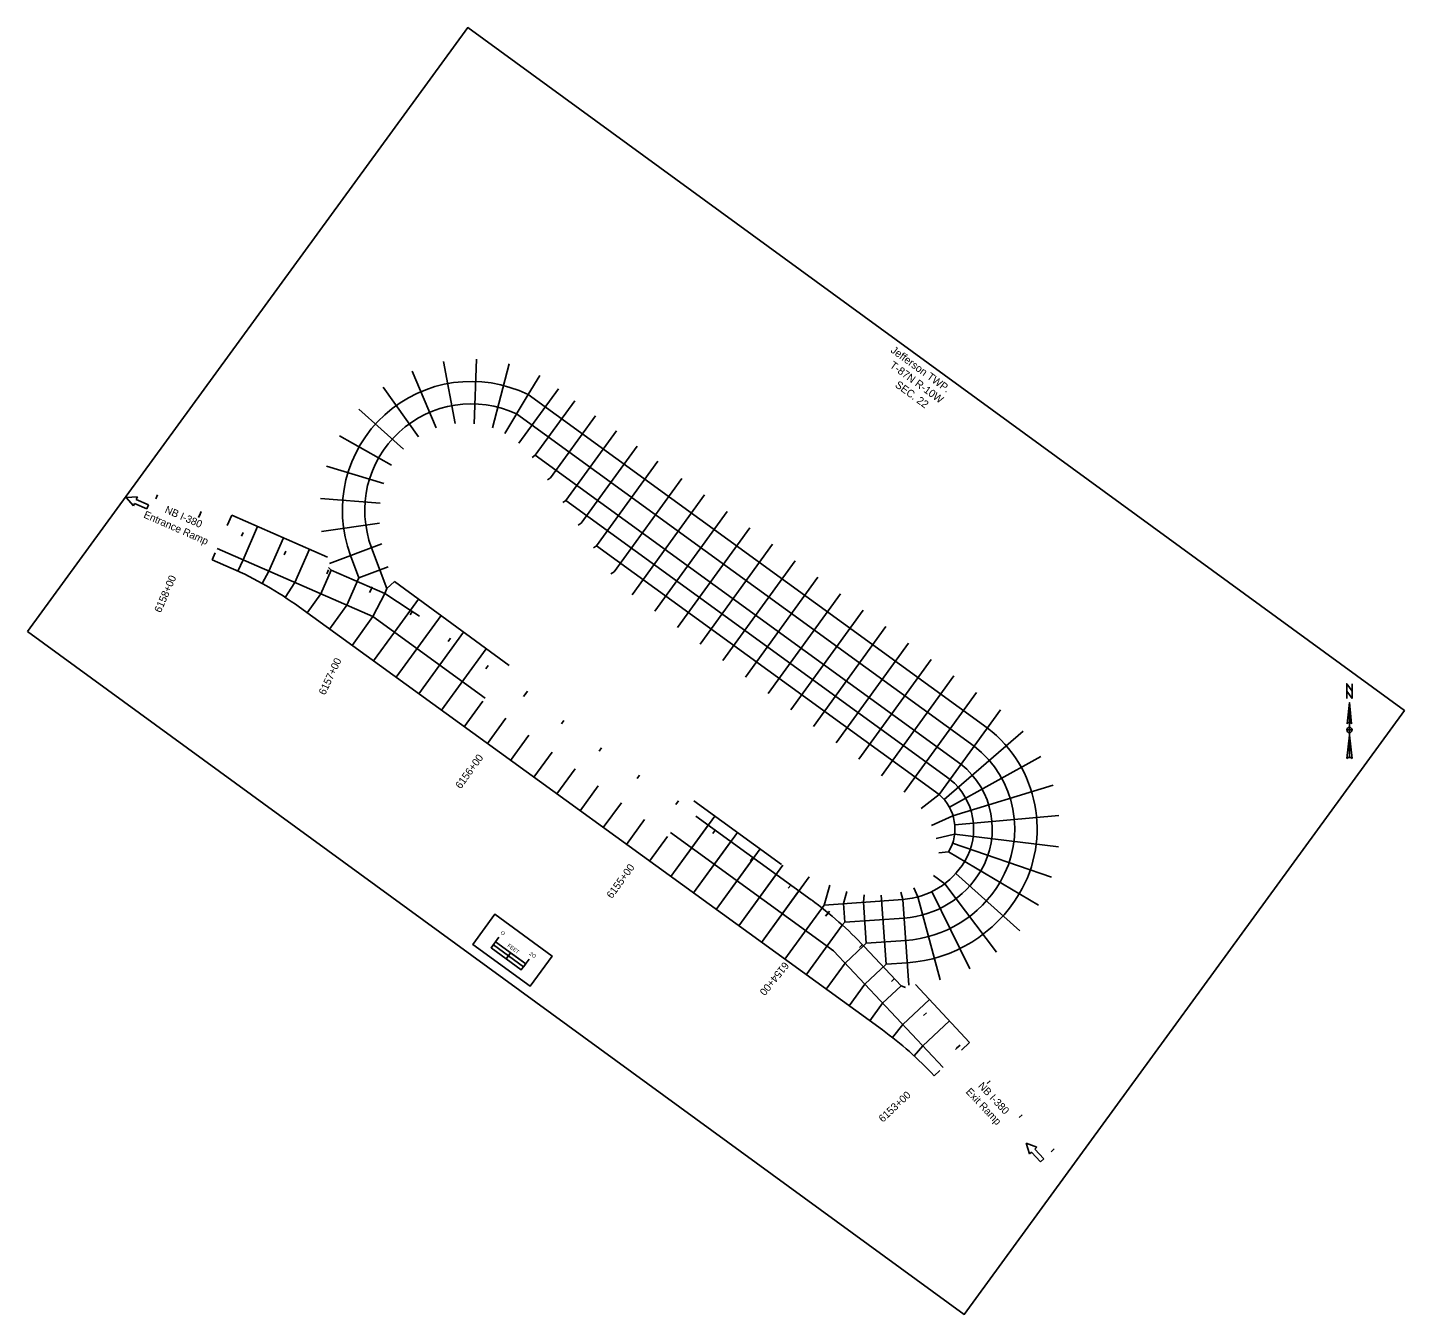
# Model space of a CAD drawing. Extents: x 15567747 to 15568484, y 8782920 to 8783608.
import ezdxf

# ---------------------------------------------------------------- set-up
doc = ezdxf.new("R2010")
doc.units = 0
for name, color, linetype in [('_CIVIL_CONSTRUCTION', 7, 'Continuous'), ('Alignment', 7, 'Continuous'), ('EdgeShoulder', 7, 'Continuous'), ('EXT_SH', 7, 'Continuous'), ('Joints', 7, 'Continuous'), ('Terrain', 7, 'Continuous'), ('Text', 7, 'Continuous'), ('TextAlignment', 7, 'Continuous'), ('TextAlignmentSml', 7, 'Continuous')]:
    doc.layers.add(name, color=color, linetype=linetype)

msp = doc.modelspace()

# ---------------------------------------------------------------- linework, layer by layer
at = {"layer": '_CIVIL_CONSTRUCTION'}
msp.add_lwpolyline([(15567746.92, 8783285.1), (15568248.32, 8782919.55), (15568483.96, 8783242.77), (15567982.56, 8783608.32)], close=True, dxfattribs=at)
at = {"layer": 'Alignment'}
for p, q in [((15567799.72, 8783356.86), (15567805.71, 8783357.17)), ((15567803.56, 8783352.25), (15567799.72, 8783356.86)), ((15567804.16, 8783353.62), (15567803.56, 8783352.25)), ((15567810.71, 8783350.75), (15567804.16, 8783353.62)), ((15567805.71, 8783357.17), (15567805.11, 8783355.8)), ((15567805.11, 8783355.8), (15567811.67, 8783352.93)), ((15567811.67, 8783352.93), (15567810.71, 8783350.75)), ((15568283.23, 8783005.44), (15568281.51, 8783011.19)), ((15568281.51, 8783011.19), (15568287.14, 8783009.12)), ((15568284.31, 8783006.46), (15568283.23, 8783005.44)), ((15568289.21, 8783001.25), (15568284.31, 8783006.46)), ((15568287.14, 8783009.12), (15568286.05, 8783008.1)), ((15568286.05, 8783008.1), (15568290.95, 8783002.88)), ((15568290.95, 8783002.88), (15568289.21, 8783001.25))]:
    msp.add_line(p, q, dxfattribs=at)
at = {"layer": 'EdgeShoulder'}
for p, q in [((15567856.21, 8783347.29), (15567853.8, 8783341.79)), ((15567907.4, 8783324.87), (15567856.21, 8783347.29)), ((15567845.8, 8783323.47), (15567847.4, 8783327.13)), ((15567855.98, 8783319.01), (15567845.8, 8783323.47)), ((15567943.42, 8783311.77), (15568004.64, 8783266.94)), ((15567892.42, 8783298.14), (15568204.49, 8783071.81)), ((15568150.43, 8783160.43), (15568103.49, 8783194.47)), ((15568251.21, 8783065.15), (15568222.15, 8783096.08)), ((15568251.21, 8783065.15), (15568246.84, 8783061.04)), ((15568232.26, 8783047.34), (15568235.18, 8783050.08))]:
    msp.add_line(p, q, dxfattribs=at)
for centre, start, end in [((15567777.35, 8783139.47), 54.04815, 66.34808), ((15568089.41, 8782913.14), 43.21229, 54.04815)]:
    msp.add_arc(centre, 196, start, end, dxfattribs=at)
at = {"layer": 'Joints'}
for p, q in [((15567975.79, 8783396.33), (15567969.6, 8783429.57)), ((15567986.01, 8783396.3), (15567987.19, 8783430.89)), ((15567995.79, 8783394.03), (15568004.64, 8783428.37)), ((15567965.68, 8783394.01), (15567952.72, 8783424.47)), ((15567956.26, 8783389.35), (15567937.34, 8783415.84)), ((15568009.92, 8783385.8), (15568031.07, 8783414.93)), ((15568014.89, 8783411.84), (15568260.68, 8783233.47)), ((15568018.69, 8783379.43), (15568039.83, 8783408.57)), ((15567948.12, 8783382.58), (15567924.19, 8783404.09)), ((15568008.71, 8783401.5), (15568253.63, 8783223.76)), ((15568026.88, 8783367.31), (15568050.96, 8783400.49)), ((15567941.75, 8783374.03), (15567913.9, 8783389.77)), ((15568035.07, 8783355.19), (15568062.09, 8783392.42)), ((15568043.26, 8783343.06), (15568073.22, 8783384.34)), ((15568018.69, 8783379.43), (15568017.05, 8783378.23)), ((15568018.69, 8783379.43), (15568246.58, 8783214.04)), ((15568051.45, 8783330.94), (15568084.35, 8783376.26)), ((15567937.57, 8783364.22), (15567906.95, 8783373.56)), ((15568026.88, 8783367.31), (15568025.22, 8783366.19)), ((15568060.86, 8783317.02), (15568097.13, 8783366.99)), ((15567816.48, 8783358.14), (15567815.6, 8783356.14)), ((15567935.63, 8783353.74), (15567903.67, 8783356.23)), ((15568035.07, 8783355.19), (15568033.41, 8783354.07)), ((15568035.07, 8783355.19), (15568240.71, 8783205.95)), ((15568070.5, 8783304.76), (15568109.27, 8783358.18)), ((15567838.89, 8783346.99), (15567839.87, 8783349.23)), ((15568082.64, 8783295.95), (15568121.41, 8783349.37)), ((15567862.28, 8783338.08), (15567861.4, 8783336.08)), ((15567870.07, 8783341.22), (15567862.28, 8783323.37)), ((15567935.27, 8783342.99), (15567904.22, 8783338.6)), ((15568043.26, 8783343.06), (15568041.61, 8783341.95)), ((15568094.78, 8783287.14), (15568133.55, 8783340.56)), ((15567883.94, 8783335.15), (15567876.16, 8783317.31)), ((15567908.58, 8783321.51), (15567936.51, 8783331.98)), ((15568051.45, 8783330.94), (15568049.8, 8783329.82)), ((15568051.45, 8783330.94), (15568234.83, 8783197.86)), ((15568106.92, 8783278.33), (15568145.69, 8783331.75)), ((15567848.4, 8783329.42), (15567931.83, 8783293.03)), ((15567862.28, 8783323.37), (15567859.53, 8783317.41)), ((15567885.18, 8783328.05), (15567884.3, 8783326.05)), ((15567897.81, 8783329.07), (15567890.04, 8783311.26)), ((15567919.81, 8783325.72), (15567924.28, 8783313.81)), ((15567931.05, 8783329.93), (15567939.21, 8783308.17)), ((15567876.16, 8783317.31), (15567872.54, 8783310.8)), ((15567909.45, 8783317.9), (15567903.91, 8783305.2)), ((15567908.08, 8783318.02), (15567907.2, 8783316.02)), ((15567924.28, 8783313.81), (15567939.94, 8783319.67)), ((15568060.86, 8783317.02), (15568059.21, 8783315.9)), ((15568119.06, 8783269.52), (15568157.83, 8783322.94)), ((15567890.04, 8783311.26), (15567884.85, 8783303.36)), ((15567924.28, 8783313.81), (15567917.87, 8783299.11)), ((15567930.42, 8783306.81), (15567931.47, 8783309.03)), ((15567939.21, 8783308.17), (15567943.42, 8783311.77)), ((15568131.2, 8783260.71), (15568169.97, 8783314.13)), ((15567903.91, 8783305.2), (15567896.59, 8783295.11)), ((15567938.17, 8783305.37), (15567938.23, 8783305.35)), ((15567938.17, 8783305.37), (15567951.82, 8783296.51)), ((15567938.23, 8783305.34), (15567939.21, 8783308.17)), ((15568143.34, 8783251.9), (15568182.11, 8783305.32)), ((15567917.87, 8783299.11), (15567908.63, 8783286.38)), ((15567944.26, 8783260.55), (15567968.24, 8783293.59)), ((15567952.83, 8783295.86), (15567951.66, 8783294.02)), ((15567951.82, 8783296.51), (15567956.69, 8783293.34)), ((15568155.48, 8783243.09), (15568194.25, 8783296.51)), ((15567931.83, 8783293.03), (15567991.87, 8783249.48)), ((15568167.62, 8783234.28), (15568206.39, 8783287.7)), ((15567956.4, 8783251.74), (15567980.34, 8783284.73)), ((15567973.28, 8783281.49), (15567972, 8783279.72)), ((15568179.76, 8783225.47), (15568218.53, 8783278.89)), ((15567968.54, 8783242.93), (15567992.45, 8783275.87)), ((15567993.52, 8783266.81), (15567992.24, 8783265.05)), ((15568191.9, 8783216.66), (15568230.67, 8783270.08)), ((15568204.04, 8783207.85), (15568242.81, 8783261.26)), ((15568013.04, 8783251.14), (15568014.47, 8783253.13)), ((15568216.18, 8783199.04), (15568254.95, 8783252.45)), ((15567980.71, 8783234.1), (15567990.58, 8783247.71)), ((15568267.73, 8783243.18), (15568234.83, 8783197.86)), ((15567993.11, 8783225.11), (15568002.95, 8783238.67)), ((15568033.99, 8783237.46), (15568032.71, 8783235.69)), ((15568005.51, 8783216.11), (15568015.32, 8783229.63)), ((15568279.86, 8783231.8), (15568237.5, 8783195.16)), ((15568017.91, 8783207.12), (15568027.68, 8783220.58)), ((15568054.23, 8783222.78), (15568052.95, 8783221.01)), ((15568289.37, 8783218.16), (15568240.36, 8783191.07)), ((15568030.31, 8783198.13), (15568040.05, 8783211.54)), ((15568074.47, 8783208.1), (15568073.19, 8783206.33)), ((15568042.72, 8783189.13), (15568052.42, 8783202.5)), ((15568234.83, 8783197.86), (15568225.29, 8783190.33)), ((15568295.86, 8783202.85), (15568242.3, 8783186.48)), ((15568055.12, 8783180.14), (15568064.78, 8783193.45)), ((15568093.99, 8783192.43), (15568095.43, 8783194.42)), ((15568067.52, 8783171.14), (15568077.15, 8783184.41)), ((15568091.24, 8783153.93), (15568114.74, 8783186.31)), ((15568104.66, 8783186.2), (15568166.47, 8783141.38)), ((15568242.3, 8783186.48), (15568230.86, 8783181.23)), ((15568299.04, 8783186.52), (15568243.26, 8783181.58)), ((15568091.09, 8783177.52), (15568178.32, 8783114.25)), ((15568091.09, 8783177.52), (15568178.32, 8783114.25)), ((15568091.24, 8783153.93), (15568111.21, 8783181.45)), ((15568103.38, 8783145.12), (15568126.88, 8783177.5)), ((15568114.94, 8783178.75), (15568113.66, 8783176.98)), ((15568243.18, 8783176.59), (15568233.37, 8783174.3)), ((15568298.78, 8783169.89), (15568243.18, 8783176.59)), ((15568079.92, 8783162.14), (15568089.52, 8783175.37)), ((15568103.38, 8783145.12), (15568123.35, 8783172.64)), ((15568115.52, 8783136.31), (15568139.02, 8783168.7)), ((15568295.08, 8783153.68), (15568242.07, 8783171.73)), ((15568115.52, 8783136.31), (15568135.49, 8783163.83)), ((15568135.18, 8783164.07), (15568133.9, 8783162.3)), ((15568239.98, 8783167.2), (15568234.75, 8783166.7)), ((15568288.11, 8783138.58), (15568239.98, 8783167.2)), ((15568127.66, 8783127.5), (15568151.26, 8783160.03)), ((15568127.66, 8783127.5), (15568147.63, 8783155.02)), ((15568139.8, 8783118.69), (15568165.25, 8783153.76)), ((15568237.85, 8783150.09), (15568231.94, 8783154.54)), ((15568278.1, 8783124.92), (15568243.79, 8783155.57)), ((15568139.8, 8783118.69), (15568159.77, 8783146.21)), ((15568155.42, 8783149.39), (15568154.14, 8783147.62)), ((15568173.38, 8783138.68), (15568176.39, 8783149.23)), ((15568223.41, 8783143), (15568221.4, 8783147.92)), ((15568265.65, 8783113.44), (15568237.85, 8783150.09)), ((15568215.44, 8783141.66), (15568173.38, 8783138.68)), ((15568183.68, 8783139.41), (15568185.55, 8783145.96)), ((15568184.39, 8783129.43), (15568183.68, 8783139.41)), ((15568194.31, 8783140.16), (15568194.74, 8783144.17)), ((15568195.87, 8783118.22), (15568194.31, 8783140.16)), ((15568206.46, 8783106.94), (15568203.84, 8783143.95)), ((15568215.44, 8783141.66), (15568214.42, 8783145.61)), ((15568218.69, 8783095.77), (15568215.44, 8783141.66)), ((15568235.39, 8783098.59), (15568223.41, 8783143)), ((15568251.24, 8783104.55), (15568230.97, 8783145.85)), ((15568173.38, 8783138.68), (15568152.32, 8783109.64)), ((15568174.69, 8783133.51), (15568176.24, 8783135.41)), ((15568216.14, 8783131.68), (15568184.39, 8783129.43)), ((15568183.05, 8783127.95), (15568163.75, 8783101.35)), ((15568184.39, 8783129.43), (15568183.05, 8783127.95)), ((15568193.8, 8783117.49), (15568192.22, 8783115.98)), ((15568195.87, 8783118.22), (15568194.41, 8783116.84)), ((15568216.99, 8783119.71), (15568195.87, 8783118.22)), ((15568237, 8783051.79), (15568178.32, 8783114.25)), ((15568214.49, 8783095.47), (15568194.81, 8783116.42)), ((15568206.46, 8783106.94), (15568195.17, 8783096.32)), ((15568217.84, 8783107.74), (15568206.46, 8783106.94)), ((15568195.17, 8783096.32), (15568186.73, 8783084.69)), ((15568210.92, 8783099.27), (15568209.33, 8783097.78)), ((15568216.96, 8783094.5), (15568214.49, 8783095.47)), ((15568228.04, 8783081.05), (15568226.45, 8783079.55)), ((15568244.26, 8783061.99), (15568246.05, 8783063.67)), ((15568262.27, 8783044.61), (15568260.68, 8783043.11)), ((15568279.39, 8783026.39), (15568277.8, 8783024.89)), ((15568296.51, 8783008.17), (15568294.92, 8783006.67))]:
    msp.add_line(p, q, dxfattribs=at)
for points in [[(15568002.46, 8783391.04), (15568014.89, 8783411.84), (15568021.14, 8783422.13)], [(15567908.08, 8783319.36), (15567909.45, 8783317.9), (15567938.17, 8783305.37)], [(15567920.67, 8783277.65), (15567931.83, 8783293.03), (15567938.23, 8783305.34)], [(15567932.12, 8783269.36), (15567943.27, 8783284.73), (15567956.14, 8783302.46)], [(15568194.41, 8783116.84), (15568184.57, 8783107.6), (15568174.43, 8783093.61)], [(15568214.49, 8783095.47), (15568204.65, 8783086.23), (15568197.74, 8783076.7)], [(15568229.64, 8783088.1), (15568215.43, 8783074.75), (15568209.94, 8783067.71)], [(15568240.43, 8783076.62), (15568226.22, 8783063.27), (15568221.43, 8783058.02)]]:
    msp.add_lwpolyline(points, dxfattribs=at)
for centre, radius, start, end in [((15567984.43, 8783349.93), 69, 63.80054, 200.54331), ((15567984.43, 8783349.93), 57, 64.78265, 200.54331), ((15568219.35, 8783179.46), 68, 329.26491, 52.57377), ((15568219.35, 8783179.46), 56, 329.26491, 52.26157), ((15568219.35, 8783179.46), 44, 329.26491, 51.77896), ((15568219.35, 8783179.46), 34, 329.26491, 51.11629), ((15568219.35, 8783179.46), 24, 329.26491, 49.90032), ((15568212.47, 8783183.55), 42, 274.04757, 329.26491), ((15568212.47, 8783183.55), 52, 274.04757, 329.26491), ((15568212.47, 8783183.55), 64, 274.04757, 329.26491), ((15568049.05, 8782979.48), 200, 43.21229, 54.04815), ((15568212.47, 8783183.55), 76, 274.04757, 329.26491)]:
    msp.add_arc(centre, radius, start, end, dxfattribs=at)
at = {"layer": 'Terrain'}
for p, q in [((15567839.38, 8783348.11), (15567838.5, 8783346.11)), ((15567930.95, 8783307.92), (15567930.01, 8783305.94)), ((15568013.76, 8783252.14), (15568012.47, 8783250.37)), ((15568175.46, 8783134.46), (15568174.08, 8783132.77)), ((15568245.16, 8783062.83), (15568243.56, 8783061.33))]:
    msp.add_line(p, q, dxfattribs=at)
at = {"layer": 'Text'}
msp.add_line((15568003.15, 8783109.92), (15568005.51, 8783113.15), dxfattribs=at)
msp.add_line((15568003.15, 8783109.92), (15568005.51, 8783113.15), dxfattribs=at)
for points in [[(15567985.21, 8783117.56), (15567996.99, 8783133.72), (15568027.7, 8783111.33), (15568015.91, 8783095.17)], [(15567995.07, 8783115.81), (15568003.15, 8783109.92), (15568004.34, 8783111.55), (15567996.26, 8783117.44)], [(15568004.34, 8783111.55), (15568012.42, 8783105.66), (15568013.59, 8783107.26), (15568005.51, 8783113.15)]]:
    msp.add_lwpolyline(points, close=True, dxfattribs=at)
for points in [[(15567999.2, 8783121.47), (15567995.07, 8783115.81), (15568011.23, 8783104.03), (15568015.36, 8783109.69)], [(15567997.43, 8783119.04), (15568013.59, 8783107.26)]]:
    msp.add_lwpolyline(points, dxfattribs=at)
at = {"layer": 'TextAlignmentSml'}
for p, q in [((15568454.51, 8783247.01), (15568455.63, 8783235.74)), ((15568454.51, 8783247.01), (15568454.51, 8783217.72)), ((15568453.38, 8783235.74), (15568453.38, 8783235.74)), ((15568453.43, 8783235.84), (15568453.64, 8783236.08)), ((15568453.1, 8783217.15), (15568454.51, 8783229.54)), ((15568454.51, 8783230.95), (15568454.51, 8783230.95))]:
    msp.add_line(p, q, dxfattribs=at)
for points in [[(15568455.92, 8783249.26), (15568453.1, 8783253.2), (15568453.1, 8783257.14), (15568455.92, 8783253.2)], [(15567996.99, 8783133.72), (15568027.7, 8783111.33), (15568015.91, 8783095.17), (15567985.21, 8783117.56)]]:
    msp.add_lwpolyline(points, close=True, dxfattribs=at)
for points in [[(15568453.1, 8783249.26), (15568453.1, 8783257.14), (15568455.92, 8783253.2), (15568455.92, 8783257.14)], [(15568453.38, 8783235.74), (15568454.51, 8783247.01), (15568454.51, 8783236.3)], [(15568454.51, 8783230.95), (15568454.51, 8783232.36), (15568453.1, 8783232.36)], [(15568455.92, 8783232.36), (15568454.51, 8783232.36), (15568454.51, 8783233.77)], [(15568454.51, 8783217.72), (15568454.51, 8783229.54), (15568455.92, 8783217.15)]]:
    msp.add_lwpolyline(points, dxfattribs=at)
for centre, radius, start, end in [((15568454.51, 8783234.9), 1.41, 90.02039, 143.12574), ((15568454.51, 8783234.9), 1.41, 36.84806, 90.02184), ((15568454.51, 8783232.36), 1.41, 90, 180), ((15568454.51, 8783232.36), 1.41, 180, 270), ((15568454.51, 8783232.36), 1.41, 360, 90), ((15568454.51, 8783232.36), 1.41, 270, 360), ((15568454.51, 8783215.68), 2.04, 89.98939, 133.61895), ((15568454.51, 8783215.67), 2.04, 46.40206, 90.00064)]:
    msp.add_arc(centre, radius, start, end, dxfattribs=at)

# ---------------------------------------------------------------- texts
at = {"layer": 'EXT_SH'}
for s, rotation, p in [('Entrance Ramp', 336.34808, (15567808.69, 8783346.18)), ('NB I-380', 336.34808, (15567820.04, 8783348.83)), ('NB I-380', 313.21229, (15568255.49, 8783041.62)), ('Exit Ramp', 313.21229, (15568248.86, 8783038.49))]:
    msp.add_text(s, height=3.99, rotation=rotation, dxfattribs=at).set_placement(p)
at = {"layer": 'Joints'}
for s, rotation, p in [('6158+00', 66.34808, (15567818.23, 8783294.81)), ('6157+00', 64.72153, (15567906.15, 8783250.72)), ('6156+00', 54.04815, (15567978.8, 8783200.52)), ('6155+00', 54.04815, (15568059.75, 8783141.81)), ('6154+00', 230.79607, (15568151.79, 8783108.6)), ('6153+00', 43.21229, (15568204.76, 8783022.13))]:
    msp.add_text(s, height=4.008, rotation=rotation, dxfattribs=at).set_placement(p)
at = {"layer": 'Text'}
for s, p in [('O', (15567999.85, 8783123.47)), ('FEET', (15568003.55, 8783116.56)), ('2O', (15568015.22, 8783112.26))]:
    msp.add_text(s, height=2, rotation=323.90553, dxfattribs=at).set_placement(p)
at = {"layer": 'TextAlignment'}
for s, p in [('Jefferson TWP.', (15568208.58, 8783434.83)), ('T-87N R-10W', (15568208.11, 8783426.76)), ('SEC. 22', (15568210.94, 8783416.28))]:
    msp.add_text(s, height=4.08, rotation=323.90553, dxfattribs=at).set_placement(p)

doc.saveas('drawing.dxf')
